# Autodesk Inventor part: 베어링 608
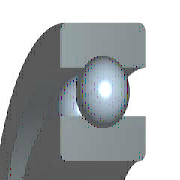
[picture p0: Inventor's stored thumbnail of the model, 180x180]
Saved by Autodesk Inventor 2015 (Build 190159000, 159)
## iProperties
IsCustomPart: 1
Company: 한국ATC센터
Created: 2014-07
Part Number: 베어링 608
Material: 강, 연강
Description: 깊은 그루브 볼 베어링
Document SubType Name: Modeling
Standard: KS B 2023
Designer: KYOUNG IL JANG
Standards Organization: KS
Language: ko-KR
Size Designation: 608 - 8 x 22 x 7
Categories: <MemberInstance><Categories><Category DisplayName="샤프트 부품" InternalName="7f7aeb1f-a693-4053-b835-cee3144e0d98" Mnemonic="SHFT"><Category DisplayName="베어링" Inter
Density: 1 g/cm^3
Appearance: 강철
Author: KYOUNG IL JANG
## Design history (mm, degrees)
sketch "스케치" dims "d0" = 3.64 (= -0.26 x WD + 0.26 x BD)
  geometry: L1 (1.68, 7.5)-(5.32, 7.5); L2 (3.5, 7.5)-(3.5, 5.68); L3 (3.5, 7.5)-(3.5, 9.32); L4 (2.148, 6.282)-(0, 6.282); L5 (0, 4)-(7, 4); L6 (2.148, 8.718)-(0, 8.718); L7 (0, 11)-(7, 11); L8 (7, 4)-(7, 6.282); L9 (4.852, 6.282)-(7, 6.282); L10 (4.852, 8.718)-(7, 8.718); L11 (7, 11)-(7, 8.718); L12 (-1.4, 0)-(8.4, 0) reference; L13 (0, -0.3)-(0, 5.3) reference
  constraints: 22 end point, 4 point on line, 2 collinear, 2 perpendicular, 2 symmetric about line, 1 midpoint, 1 parallel, 14 other
  dimensions: "d9" = 8 diameter of L5 L12 (= WD); "d11" = 22 diameter of L7 L12 (= BD); "d12" = 7 distance between parallel lines of L8 L13 (= KB); "d13" = 12.564 diameter of L9 L12 (= 0.326 x BD + 0.674 x WD)
revolve "본체" stored, may be unused: angle "d6" = 90 deg
revolve "볼" stored, may be unused: angle "d7" = 90 deg
pattern_circular "IDS_ARRAYBALL[SIMPL:T]" dims angle "d3" = 360 deg
body "Solid1"
fillet "모깎기1" dims "d1" = 0.3 (= KRS)
other parameters: "WD" = 8 [user parameter; used in 5 equation terms], "BD" = 22 [user parameter; used in 5 equation terms], "KB" = 7 [user parameter; used in 1 equation term], "KRS" = 0.3 [user parameter; used in 1 equation term], "d4" = 0, "d5" = 0, "d8" = 0, "d14" = 0, "d15" = 0, "BBA" = 0 [user parameter], "BC0" = 1370000 [user parameter], "BC" = 3250000 [user parameter], "BR" = 11 (= 0.5 x BD) [user parameter], "WR" = 4 (= 0.5 x WD) [user parameter]
